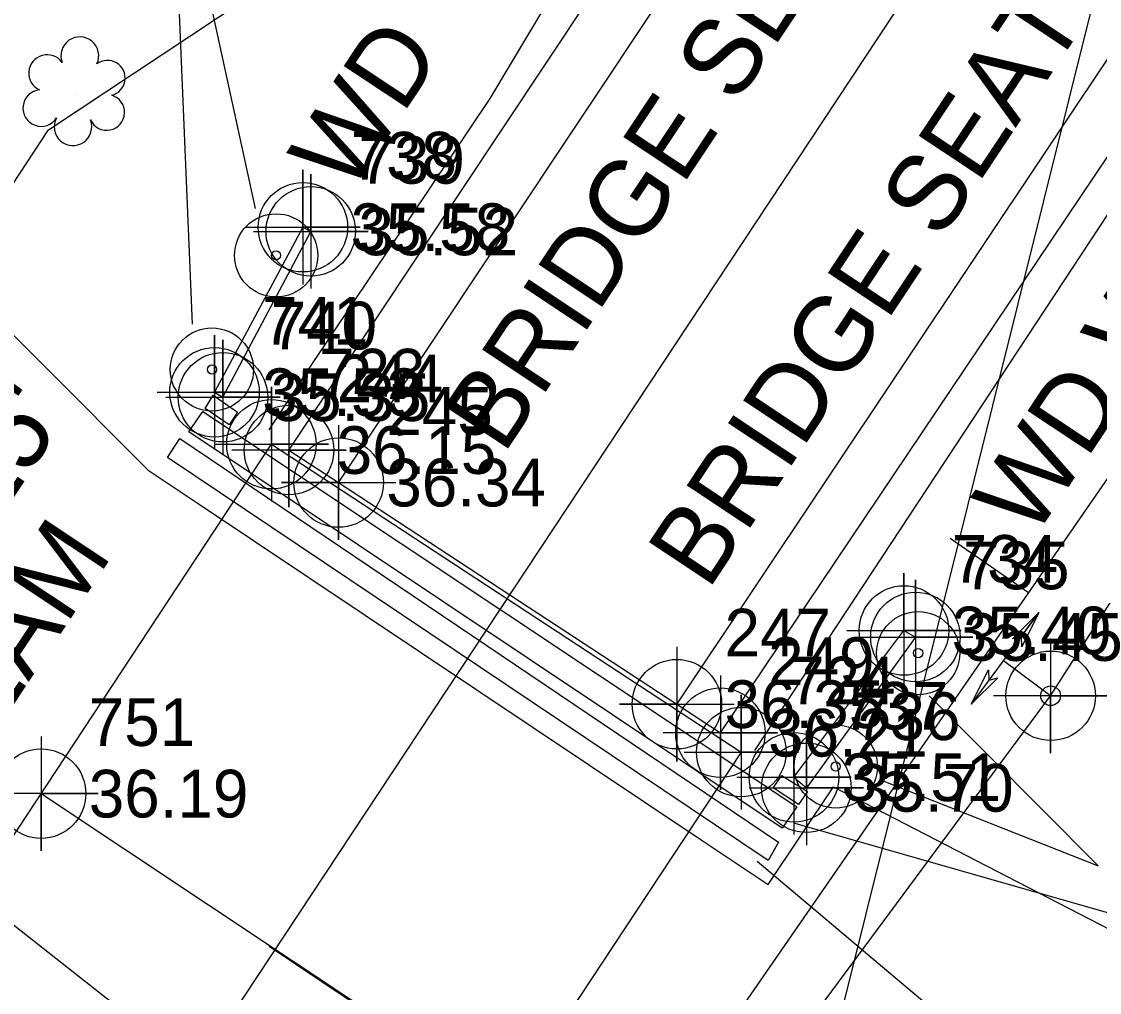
# Model space of a CAD drawing. Extents: x 2603627 to 2605187, y 896619 to 899063.
# Drawn here: x 2604536.5 to 2604593, y 898167.5 to 898218.4 of the extents above; entities that cross this region are included whole.
import ezdxf

# ---------------------------------------------------------------- set-up
doc = ezdxf.new("R2010")
doc.units = 0
for name, color, linetype in [('Exist Guardrail', 7, 'Continuous'), ('Exist Horizontal Alignment', 7, 'Continuous'), ('Exist Horizontal Baseline Alignment', 7, 'Continuous'), ('Exist Horizontal Baseline Alignment Tick small', 7, 'Continuous'), ('Exist Hydro Stream or Body of Water', 7, 'Continuous'), ('Exist Other Culture Located Object CELL', 7, 'Continuous'), ('Exist Other Culture Located Object Leader', 7, 'Continuous'), ('Exist Property Tie Line', 7, 'Continuous'), ('Exist Roads EOP', 7, 'Continuous'), ('Exist Roads EOP Cogo Elevation', 7, 'Continuous'), ('Exist Roads EOP Cogo Number', 7, 'Continuous'), ('Exist Roads EOP Cogo Point CELL', 7, 'Continuous'), ('Exist Roads EOT', 7, 'Continuous'), ('Exist Roads EOT Cogo Elevation', 7, 'Continuous'), ('Exist Roads EOT Cogo Number', 7, 'Continuous'), ('Exist Roads EOT Cogo Point CELL', 7, 'Continuous'), ('Exist Structure Major Bridge Seam', 7, 'Continuous'), ('Exist Structure Major Bridge Seam Cogo Elevation', 7, 'Continuous'), ('Exist Structure Major Bridge Seam Cogo Number', 7, 'Continuous'), ('Exist Structure Major Bridge Seam Cogo Point CELL', 7, 'Continuous'), ('Exist Structure Major Bridge Seat Top Elevation', 7, 'Continuous'), ('Exist Structure Major Bridge Topo', 7, 'Continuous'), ('Exist Structure Major Bridge Topo Leader', 7, 'Continuous'), ('Exist Structure Major Bridge Topo Text', 7, 'Continuous'), ('Exist Structure Major Bridge WW', 7, 'Continuous'), ('Exist Structure Major Bridge WW Cogo Elevation', 7, 'Continuous'), ('Exist Structure Major Bridge WW Cogo Number', 7, 'Continuous'), ('Exist Structure Major Bridge WW Cogo Point CELL', 7, 'Continuous'), ('Exist Structure Major Bridge WW Leader', 7, 'Continuous'), ('Exist Structure Major Bridge WW Text', 7, 'Continuous'), ('Exist Structure Major Deck Tunnel Box Culvert', 7, 'Continuous'), ('Exist Structure Major Deck Tunnel Box Culvert Cogo Number', 7, 'Continuous'), ('Exist Structure Major Deck Tunnel Box Culvert Cogo Point CELL', 7, 'Continuous'), ('Exist Utilities Telephone UG FO SUE LOS C', 7, 'Continuous'), ('Exist Utilities Water Change of Service SUE CELL', 7, 'Continuous'), ('Exist Utilities Water UG Line SUE LOS B', 7, 'Continuous'), ('Exist Utilities Water UG Line SUE LOS B Cogo Point CELL', 7, 'Continuous'), ('Exist Utilities Water UG Line SUE LOS C', 7, 'Continuous'), ('Exist Vegetation Shrub CELL', 7, 'Continuous')]:
    doc.layers.add(name, color=color, linetype=linetype)

# ---------------------------------------------------------------- blocks, each defined once
blk = doc.blocks.new('EXIST UTILITIES WATER UG LINE SUE LOS B COGO POINT')
at = {"layer": 'Exist Utilities Water UG Line SUE LOS B Cogo Point CELL'}
blk.add_lwpolyline([(0, 0.06), (0, -0.06), (0, 0), (0.06, 0), (-0.06, 0)], dxfattribs=at)
blk.add_circle((0, 0), 0.0469, dxfattribs=at)
blk = doc.blocks.new('EXIST STRUCTURE MAJOR DECK TUNNEL BOX CULVERT COGO POINT')
at = {"layer": 'Exist Structure Major Deck Tunnel Box Culvert Cogo Point CELL'}
blk.add_lwpolyline([(-0.06, 0), (0.06, 0), (0, 0), (0, 0.06), (0, -0.06)], dxfattribs=at)
blk.add_circle((0, 0), 0.0469, dxfattribs=at)
blk = doc.blocks.new('EXIST BRIDGE SEAM COGO POINT')
at = {"layer": 'Exist Structure Major Bridge Seam Cogo Point CELL'}
blk.add_lwpolyline([(0, 0.06), (0, -0.06), (0, 0), (0.06, 0), (-0.06, 0)], dxfattribs=at)
blk.add_circle((0, 0), 0.0469, dxfattribs=at)
blk = doc.blocks.new('EXIST ROADS EOP COGO POINT')
at = {"layer": 'Exist Roads EOP Cogo Point CELL'}
blk.add_lwpolyline([(0, 0.06), (0, -0.06), (0, 0), (0.06, 0), (-0.06, 0)], dxfattribs=at)
blk.add_circle((0, 0), 0.0469, dxfattribs=at)
blk = doc.blocks.new('EXIST ROADS EOT COGO POINT')
at = {"layer": 'Exist Roads EOT Cogo Point CELL'}
blk.add_lwpolyline([(0, 0.06), (0, -0.06), (0, 0), (-0.06, 0), (0.06, 0)], dxfattribs=at)
blk.add_circle((0, 0), 0.0469, dxfattribs=at)
blk = doc.blocks.new('EXIST STRUCTURE MAJOR BRIDGE WW COGO POINT')
at = {"layer": 'Exist Structure Major Bridge WW Cogo Point CELL'}
blk.add_lwpolyline([(-0.06, 0), (0.06, 0), (0, 0), (0, 0.06), (0, -0.06)], dxfattribs=at)
blk.add_circle((0, 0), 0.0469, dxfattribs=at)

msp = doc.modelspace()

# ---------------------------------------------------------------- linework, layer by layer
at = {"layer": 'Exist Guardrail'}
for points in [[(2604549.447, 898197.005), (2604551.688, 898200.424), (2604561.034, 898214.376), (2604574.047, 898236.144), (2604583.438, 898252.897), (2604603.34, 898290.06), (2604614.453, 898307.438), (2604661.781, 898380.221)], [(2604631.981, 898264.559), (2604605.99, 898227.058), (2604595.344, 898211.259), (2604574.882, 898180.207)]]:
    msp.add_lwpolyline(points, dxfattribs=at)
at = {"layer": 'Exist Horizontal Alignment'}
msp.add_line((2604537.349, 898151.011), (2604647.762, 898317.915), dxfattribs=at)
at = {"layer": 'Exist Horizontal Baseline Alignment'}
msp.add_line((2604544.961, 898124.436), (2604793.601, 898483.903), dxfattribs=at)
at = {"layer": 'Exist Horizontal Baseline Alignment Tick small'}
msp.add_line((2604589.255, 898188.473), (2604585.142, 898191.317), dxfattribs=at)
at = {"layer": 'Exist Hydro Stream or Body of Water'}
msp.add_line((2604545.668, 898193.174), (2604572.086, 898175.527), dxfattribs=at)
for points in [[(2604479.384, 898242.662), (2604480.506, 898241.559), (2604504.82, 898222.675), (2604526.692, 898211.338), (2604543.098, 898194.89), (2604545.668, 898193.174)], [(2604572.086, 898175.527), (2604575.605, 898173.177), (2604579.029, 898178.3)], [(2604579.029, 898178.3), (2604601.562, 898166.672)]]:
    msp.add_lwpolyline(points, dxfattribs=at)
at = {"layer": 'Exist Other Culture Located Object CELL'}
for centre, radius in [((2604549.811, 898206.148), 2.18), ((2604549.811, 898206.148), 0.24), ((2604546.448, 898200.17), 2.18), ((2604546.448, 898200.17), 0.24), ((2604583.466, 898185.307), 2.18), ((2604583.466, 898185.307), 0.24), ((2604579.146, 898179.368), 2.18), ((2604579.146, 898179.368), 0.24)]:
    msp.add_circle(centre, radius, dxfattribs=at)
at = {"layer": 'Exist Other Culture Located Object Leader'}
for p, q in [((2604548.734, 898208.603), (2604544.327, 898228.877)), ((2604545.428, 898202.545), (2604544.327, 898228.877)), ((2604584.036, 898183.066), (2604592.898, 898174.168)), ((2604581.494, 898178.673), (2604592.898, 898174.168))]:
    msp.add_line(p, q, dxfattribs=at)
at = {"layer": 'Exist Property Tie Line'}
for p, q in [((2604598.893, 898244.519), (2604562.447, 898098.35)), ((2604545.339, 898163.743), (2604506.2, 898194.55)), ((2604549.449, 898169.943), (2604591.342, 898142.006))]:
    msp.add_line(p, q, dxfattribs=at)
at = {"layer": 'Exist Roads EOP'}
for p, q in [((2604550.488, 898195.948), (2604577.958, 898237.274)), ((2604573.101, 898181.136), (2604600.141, 898221.379))]:
    msp.add_line(p, q, dxfattribs=at)
for points in [[(2604550.488, 898195.948), (2604553.09, 898194.244)], [(2604553.09, 898194.244), (2604562.061, 898188.367), (2604570.819, 898182.631), (2604573.101, 898181.136)]]:
    msp.add_lwpolyline(points, dxfattribs=at)
at = {"layer": 'Exist Roads EOT'}
for p, q in [((2604553.101, 898194.261), (2604580.649, 898235.671)), ((2604570.83, 898182.648), (2604598.038, 898223.4))]:
    msp.add_line(p, q, dxfattribs=at)
at = {"layer": 'Exist Structure Major Bridge Seam'}
msp.add_line((2604537.493, 898177.943), (2604562.005, 898161.67), dxfattribs=at)
at = {"layer": 'Exist Structure Major Bridge Topo'}
for p, q in [((2604544.128, 898195.556), (2604544.764, 898196.555)), ((2604544.764, 898196.555), (2604576.151, 898175.402)), ((2604575.596, 898174.44), (2604544.128, 898195.556)), ((2604576.151, 898175.402), (2604575.596, 898174.44))]:
    msp.add_line(p, q, dxfattribs=at)
at = {"layer": 'Exist Structure Major Bridge Topo Leader'}
msp.add_line((2604575.03, 898174.404), (2604587.483, 898163.92), dxfattribs=at)
at = {"layer": 'Exist Structure Major Bridge WW'}
for p, q in [((2604551.216, 898207.623), (2604546.583, 898198.976)), ((2604547.025, 898198.717), (2604551.629, 898207.405)), ((2604551.216, 898207.623), (2604551.629, 898207.405)), ((2604546.583, 898198.976), (2604547.025, 898198.717)), ((2604545.239, 898196.91), (2604545.966, 898197.964)), ((2604545.966, 898197.964), (2604577.11, 898177.246)), ((2604576.346, 898176.142), (2604545.239, 898196.91)), ((2604576.955, 898178.799), (2604582.722, 898186.493)), ((2604582.722, 898186.493), (2604583.323, 898186.151)), ((2604583.323, 898186.151), (2604577.605, 898178.25)), ((2604576.955, 898178.799), (2604577.605, 898178.25)), ((2604577.11, 898177.246), (2604576.346, 898176.142))]:
    msp.add_line(p, q, dxfattribs=at)
for points in [[(2604546.094, 898198.117), (2604546.521, 898198.815), (2604547.793, 898197.934), (2604547.346, 898197.273), (2604546.094, 898198.117)], [(2604577.669, 898178.057), (2604577.2, 898177.378), (2604575.871, 898178.246), (2604576.315, 898178.897), (2604577.669, 898178.057)]]:
    msp.add_lwpolyline(points, dxfattribs=at)
at = {"layer": 'Exist Structure Major Bridge WW Leader'}
msp.add_line((2604576.936, 898176.409), (2604600.462, 898169.701), dxfattribs=at)
at = {"layer": 'Exist Structure Major Deck Tunnel Box Culvert'}
msp.add_lwpolyline([(2604525.453, 898159.692), (2604549.566, 898196.253), (2604574.197, 898180.119), (2604549.896, 898143.345), (2604525.453, 898159.692)], dxfattribs=at)
at = {"layer": 'Exist Utilities Telephone UG FO SUE LOS C'}
for p, q in [((2604537.888, 898212.732), (2604555.472, 898224.397)), ((2604506.266, 898164.788), (2604537.888, 898212.732))]:
    msp.add_line(p, q, dxfattribs=at)
at = {"layer": 'Exist Utilities Water Change of Service SUE CELL'}
for p, q in [((2604589.799, 898187.428), (2604586.249, 898182.638)), ((2604587.932, 898184.909), (2604589.799, 898187.428)), ((2604590.411, 898183.072), (2604587.932, 898184.909)), ((2604590.411, 898183.072), (2604590.411, 898183.072))]:
    msp.add_line(p, q, dxfattribs=at)
for points in [[(2604589.799, 898187.428), (2604588.902, 898185.64), (2604588.875, 898186.182), (2604588.403, 898186.057)], [(2604586.249, 898182.638), (2604587.146, 898184.426), (2604587.172, 898183.884), (2604587.645, 898184.009)]]:
    msp.add_lwpolyline(points, close=True, dxfattribs=at)
msp.add_circle((2604590.411, 898183.072), 0.517, dxfattribs=at)
at = {"layer": 'Exist Utilities Water UG Line SUE LOS B'}
msp.add_lwpolyline([(2604590.411, 898183.072), (2604608.125, 898210.782), (2604631.329, 898247.72), (2604631.98, 898248.774), (2604637.931, 898260.896), (2604650.01, 898281.754), (2604670.128, 898312.662), (2604706.143, 898370.49), (2604744.202, 898428.792), (2604775.847, 898478.143), (2604817.618, 898541.222), (2604844.764, 898580.182), (2604876.202, 898627.221), (2604907.55, 898675.151), (2604931.687, 898711.473), (2604963.512, 898758.627), (2604991.084, 898800.904), (2605022.229, 898847.261), (2605044.126, 898880.129), (2605057.71, 898900.736)], dxfattribs=at)
at = {"layer": 'Exist Utilities Water UG Line SUE LOS C'}
msp.add_line((2604550.547, 898129.275), (2604590.411, 898183.072), dxfattribs=at)
at = {"layer": 'Exist Vegetation Shrub CELL'}
msp.add_line((2604539.296, 898214.569), (2604539.296, 898214.569), dxfattribs=at)
for centre, radius, start, end in [((2604539.525, 898216.609), 0.99, 334.8391, 200.4717), ((2604537.814, 898215.696), 0.968, 35.8908, 245.4216), ((2604540.969, 898215.438), 0.929, 284.4567, 126.0861), ((2604537.496, 898213.865), 0.955, 95.1099, 327.9534), ((2604540.934, 898213.64), 0.937, 204.9913, 73.4601), ((2604539.168, 898212.885), 0.984, 151.2797, 21.387)]:
    msp.add_arc(centre, radius, start, end, dxfattribs=at)

# ---------------------------------------------------------------- block references
at = {"layer": 'Exist Roads EOP Cogo Point CELL', "xscale": 50, "yscale": 50}
for p in [(2604550.488, 898195.948), (2604573.101, 898181.136)]:
    msp.add_blockref('EXIST ROADS EOP COGO POINT', p, dxfattribs=at)
at = {"layer": 'Exist Roads EOT Cogo Point CELL', "xscale": 50, "yscale": 50}
for p in [(2604553.09, 898194.244), (2604570.819, 898182.631)]:
    msp.add_blockref('EXIST ROADS EOT COGO POINT', p, dxfattribs=at)
at = {"layer": 'Exist Structure Major Bridge Seam Cogo Point CELL', "xscale": 50, "yscale": 50}
msp.add_blockref('EXIST BRIDGE SEAM COGO POINT', (2604537.493, 898177.943), dxfattribs=at)
at = {"layer": 'Exist Structure Major Bridge WW Cogo Point CELL', "xscale": 50, "yscale": 50}
for p in [(2604551.216, 898207.623), (2604551.629, 898207.405), (2604546.583, 898198.976), (2604547.025, 898198.717), (2604582.722, 898186.493), (2604583.323, 898186.151), (2604576.955, 898178.799), (2604577.605, 898178.25)]:
    msp.add_blockref('EXIST STRUCTURE MAJOR BRIDGE WW COGO POINT', p, dxfattribs=at)
at = {"layer": 'Exist Structure Major Deck Tunnel Box Culvert Cogo Point CELL', "xscale": 50, "yscale": 50}
for p in [(2604549.566, 898196.253), (2604574.197, 898180.119)]:
    msp.add_blockref('EXIST STRUCTURE MAJOR DECK TUNNEL BOX CULVERT COGO POINT', p, dxfattribs=at)
at = {"layer": 'Exist Utilities Water UG Line SUE LOS B Cogo Point CELL', "xscale": 50, "yscale": 50}
msp.add_blockref('EXIST UTILITIES WATER UG LINE SUE LOS B COGO POINT', (2604590.411, 898183.072), dxfattribs=at)

# ---------------------------------------------------------------- texts
at = {"layer": 'Exist Roads EOP Cogo Elevation'}
for s, p in [('36.15', (2604552.988, 898194.698)), ('36.21', (2604575.601, 898179.886))]:
    msp.add_text(s, height=2.5, dxfattribs=at).set_placement(p)
at = {"layer": 'Exist Roads EOP Cogo Number'}
for s, p in [('244', (2604552.988, 898198.448)), ('249', (2604575.601, 898183.636))]:
    msp.add_text(s, height=2.5, dxfattribs=at).set_placement(p)
at = {"layer": 'Exist Roads EOT Cogo Elevation'}
for s, p in [('36.34', (2604555.59, 898192.994)), ('36.35', (2604573.319, 898181.381))]:
    msp.add_text(s, height=2.5, dxfattribs=at).set_placement(p)
at = {"layer": 'Exist Roads EOT Cogo Number'}
for s, p in [('245', (2604555.59, 898196.744)), ('247', (2604573.319, 898185.131))]:
    msp.add_text(s, height=2.5, dxfattribs=at).set_placement(p)
at = {"layer": 'Exist Structure Major Bridge Seam Cogo Elevation'}
msp.add_text('36.19', height=2.5, dxfattribs=at).set_placement((2604539.993, 898176.693))
at = {"layer": 'Exist Structure Major Bridge Seam Cogo Number'}
msp.add_text('751', height=2.5, dxfattribs=at).set_placement((2604539.993, 898180.443))
at = {"layer": 'Exist Structure Major Bridge Seat Top Elevation'}
for s, p in [("BRIDGE SEAT=33.05'", (2604561.73, 898195.662)), ("BRIDGE SEAT=33.04'", (2604572.449, 898188.544))]:
    msp.add_text(s, height=4, rotation=56.4094, dxfattribs=at).set_placement(p)
at = {"layer": 'Exist Structure Major Bridge Topo Text'}
for s, p in [("1.25'X1.15'", (2604524.358, 898175.839)), ('I-BEAM', (2604531.081, 898175.117))]:
    msp.add_text(s, height=4, rotation=56.4094, dxfattribs=at).set_placement(p)
at = {"layer": 'Exist Structure Major Bridge WW Cogo Elevation'}
for s, p in [('35.58', (2604553.716, 898206.373)), ('35.52', (2604554.129, 898206.155)), ('35.53', (2604549.083, 898197.726)), ('35.35', (2604549.525, 898197.467)), ('35.40', (2604585.222, 898185.243)), ('35.45', (2604585.823, 898184.901)), ('35.51', (2604579.455, 898177.549)), ('35.70', (2604580.105, 898177))]:
    msp.add_text(s, height=2.5, dxfattribs=at).set_placement(p)
at = {"layer": 'Exist Structure Major Bridge WW Cogo Number'}
for s, p in [('738', (2604553.716, 898210.123)), ('739', (2604554.129, 898209.905)), ('741', (2604549.083, 898201.476)), ('740', (2604549.525, 898201.217)), ('734', (2604585.222, 898188.993)), ('735', (2604585.823, 898188.651)), ('737', (2604579.455, 898181.299)), ('736', (2604580.105, 898180.75))]:
    msp.add_text(s, height=2.5, dxfattribs=at).set_placement(p)
at = {"layer": 'Exist Structure Major Bridge WW Text'}
for p in [(2604553.657, 898209.289), (2604589.503, 898191.219)]:
    msp.add_text('WD WW', height=4, rotation=56.4785, dxfattribs=at).set_placement(p)
at = {"layer": 'Exist Structure Major Deck Tunnel Box Culvert Cogo Number'}
for s, p in [('723', (2604552.066, 898198.753)), ('724', (2604576.697, 898182.619))]:
    msp.add_text(s, height=2.5, dxfattribs=at).set_placement(p)

doc.saveas('drawing.dxf')
